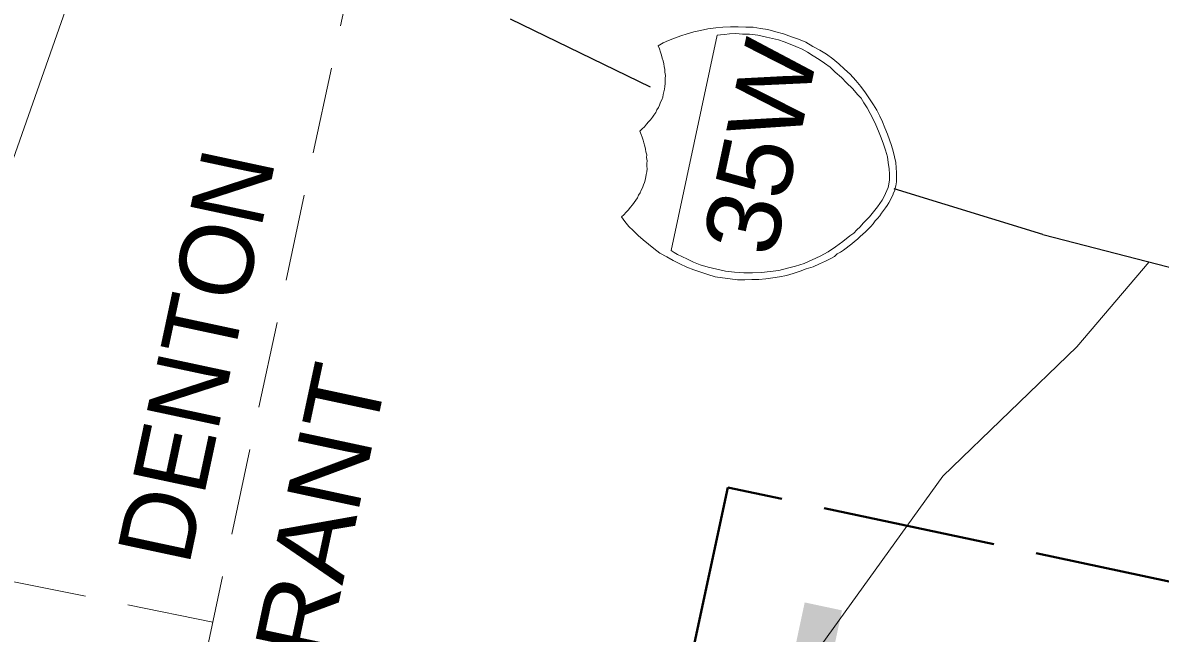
# Model space of a CAD drawing. Extents: x 2363411 to 2369126, y 6976878 to 6988319.
# Drawn here: x 2365792.5 to 2365871.2, y 6977116.7 to 6977159 of the extents above; entities that cross this region are included whole.
import ezdxf

# ---------------------------------------------------------------- set-up
doc = ezdxf.new("R2010")
doc.units = 0
doc.header["$LTSCALE"] = 2
doc.linetypes.add('LONG_DASHED', pattern=[7.5, 6, -1.5])
doc.linetypes.add('MEDIUM_DASHED', pattern=[4.5, 3, -1.5])
doc.layers.add('62', color=7, linetype='Continuous', lineweight=13)
doc.layers.add('63', color=7, linetype='Continuous', lineweight=13)

msp = doc.modelspace()

# ---------------------------------------------------------------- linework, layer by layer
at = {"layer": '62', "linetype": 'MEDIUM_DASHED'}
for p, q in [((2365864.629, 6977393.47), (2365770.962, 6976955.102)), ((2365805.658, 6977117.478), (2365712.699, 6977136.33))]:
    msp.add_line(p, q, dxfattribs=at)
at = {"layer": '62', "lineweight": 25}
for p, q in [((2365826.23, 6977159.266), (2365835.918, 6977154.55)), ((2365863.073, 6977144.33), (2365852.797, 6977147.493))]:
    msp.add_line(p, q, dxfattribs=at)
at = {"layer": '62'}
for points in [[(2365745.602, 6977025.615), (2365742.995, 6977037.011), (2365744.177, 6977051.369), (2365754.758, 6977065.562), (2365757.967, 6977076.059), (2365767.656, 6977087.91), (2365774.215, 6977096.102), (2365778.852, 6977103.376), (2365783.338, 6977114.034), (2365786.122, 6977122.873), (2365789.101, 6977134.663), (2365791.544, 6977148.682), (2365797.575, 6977165.918), (2365800.831, 6977177.279), (2365805.2, 6977190.083), (2365814.728, 6977203.211), (2365824.115, 6977215.605), (2365833.318, 6977226.804), (2365847.376, 6977238.756), (2365856.409, 6977246.882), (2365866.274, 6977257.086), (2365874.425, 6977262.384)], [(2365835.792, 6977152.114), (2365835.94, 6977152.269), (2365836.07, 6977152.447), (2365836.171, 6977152.585), (2365836.301, 6977152.764), (2365836.363, 6977152.957), (2365836.489, 6977153.115), (2365836.55, 6977153.286), (2365836.637, 6977153.474), (2365836.718, 6977153.64), (2365836.782, 6977153.835), (2365836.82, 6977154.011), (2365836.862, 6977154.209), (2365836.899, 6977154.385), (2365836.937, 6977154.561), (2365836.961, 6977154.785), (2365836.952, 6977154.948), (2365836.945, 6977155.134), (2365836.964, 6977155.338), (2365836.918, 6977155.555), (2365836.937, 6977155.737), (2365836.889, 6977155.954), (2365836.86, 6977156.144), (2365836.81, 6977156.339), (2365836.738, 6977156.54), (2365836.688, 6977156.735), (2365836.62, 6977156.954), (2365836.551, 6977157.175), (2365836.455, 6977157.38), (2365836.801, 6977157.582), (2365837.182, 6977157.756), (2365837.585, 6977157.922), (2365838.034, 6977158.079), (2365838.478, 6977158.213), (2365838.942, 6977158.345), (2365839.402, 6977158.454), (2365839.908, 6977158.554), (2365840.45, 6977158.622), (2365840.945, 6977158.676), (2365841.479, 6977158.699), (2365842.008, 6977158.703), (2365842.534, 6977158.682), (2365843.036, 6977158.667), (2365843.547, 6977158.58), (2365844.063, 6977158.517), (2365844.605, 6977158.354), (2365845.15, 6977158.215), (2365845.681, 6977158.01), (2365846.171, 6977157.836), (2365846.682, 6977157.634), (2365847.172, 6977157.346), (2365847.647, 6977157.085), (2365848.114, 6977156.801), (2365848.551, 6977156.476), (2365848.962, 6977156.137), (2365849.366, 6977155.772), (2365849.75, 6977155.414), (2365850.141, 6977154.985), (2365850.489, 6977154.565), (2365850.811, 6977154.128), (2365851.143, 6977153.646), (2365851.369, 6977153.297), (2365851.589, 6977152.927), (2365851.801, 6977152.514), (2365851.992, 6977152.125), (2365852.155, 6977151.7), (2365852.339, 6977151.27), (2365852.483, 6977150.871), (2365852.607, 6977150.476), (2365852.73, 6977150.082), (2365852.83, 6977149.692), (2365852.91, 6977149.309), (2365852.944, 6977148.932), (2365852.967, 6977148.604), (2365852.967, 6977148.283), (2365852.966, 6977147.962), (2365852.911, 6977147.697)], [(2365852.911, 6977147.697), (2365852.874, 6977147.521), (2365852.839, 6977147.367), (2365852.759, 6977147.202), (2365852.703, 6977147.051), (2365852.621, 6977146.884), (2365852.539, 6977146.718), (2365852.428, 6977146.512), (2365852.318, 6977146.329), (2365852.192, 6977146.17), (2365852.062, 6977145.991), (2365851.927, 6977145.791), (2365851.797, 6977145.61), (2365851.641, 6977145.417), (2365851.492, 6977145.262), (2365851.334, 6977145.065), (2365851.179, 6977144.871), (2365851.005, 6977144.7), (2365850.804, 6977144.514), (2365850.628, 6977144.343), (2365850.433, 6977144.178), (2365850.26, 6977144.006), (2365850.041, 6977143.844), (2365849.865, 6977143.675), (2365849.674, 6977143.532), (2365849.477, 6977143.368), (2365849.287, 6977143.224), (2365849.073, 6977143.086), (2365848.862, 6977142.971), (2365848.667, 6977142.804), (2365848.457, 6977142.688), (2365848.276, 6977142.589), (2365848.045, 6977142.477), (2365847.636, 6977142.288), (2365847.181, 6977142.087), (2365846.709, 6977141.936), (2365846.282, 6977141.77), (2365845.812, 6977141.619), (2365845.349, 6977141.491), (2365844.867, 6977141.385), (2365844.393, 6977141.325), (2365843.916, 6977141.243), (2365843.424, 6977141.209), (2365842.941, 6977141.197), (2365842.454, 6977141.187), (2365841.948, 6977141.18), (2365841.454, 6977141.239), (2365840.916, 6977141.309), (2365840.404, 6977141.394), (2365839.907, 6977141.547), (2365839.412, 6977141.7), (2365838.941, 6977141.87), (2365838.453, 6977142.064), (2365837.971, 6977142.282), (2365837.495, 6977142.523), (2365837.064, 6977142.776), (2365836.591, 6977143.037), (2365836.177, 6977143.356), (2365835.801, 6977143.641), (2365835.431, 6977143.953), (2365835.08, 6977144.257), (2365834.742, 6977144.606), (2365834.431, 6977144.881), (2365834.156, 6977145.214), (2365833.927, 6977145.539), (2365834.096, 6977145.689), (2365834.25, 6977145.862), (2365834.402, 6977146.036), (2365834.529, 6977146.193), (2365834.679, 6977146.368), (2365834.805, 6977146.525), (2365834.915, 6977146.708), (2365835.041, 6977146.865), (2365835.1, 6977147.037), (2365835.224, 6977147.196), (2365835.289, 6977147.389), (2365835.371, 6977147.556), (2365835.461, 6977147.765), (2365835.518, 6977147.917), (2365835.555, 6977148.093), (2365835.603, 6977148.312), (2365835.64, 6977148.486), (2365835.678, 6977148.664), (2365835.698, 6977148.868), (2365835.692, 6977149.051), (2365835.684, 6977149.237), (2365835.699, 6977149.418), (2365835.661, 6977149.659), (2365835.674, 6977149.838), (2365835.624, 6977150.033), (2365835.597, 6977150.223), (2365835.551, 6977150.439), (2365835.482, 6977150.661), (2365835.431, 6977150.856), (2365835.36, 6977151.057), (2365835.286, 6977151.255), (2365835.194, 6977151.483), (2365835.366, 6977151.63), (2365835.516, 6977151.78), (2365835.669, 6977151.956), (2365835.792, 6977152.114)], [(2365832.332, 6977103.289), (2365834.117, 6977103.46), (2365839.362, 6977109.264), (2365847.746, 6977115.874), (2365856.16, 6977127.585), (2365865.436, 6977136.53), (2365870.448, 6977142.431)]]:
    msp.add_lwpolyline(points, dxfattribs=at)
msp.add_lwpolyline([(2365840.551, 6977158.116), (2365837.366, 6977143.219), (2365837.569, 6977143.084), (2365837.811, 6977142.938), (2365838.103, 6977142.785), (2365838.5, 6977142.606), (2365838.918, 6977142.404), (2365839.382, 6977142.211), (2365839.922, 6977142.049), (2365840.519, 6977141.921), (2365841.135, 6977141.79), (2365841.759, 6977141.704), (2365842.394, 6977141.66), (2365842.994, 6977141.669), (2365843.619, 6977141.697), (2365844.208, 6977141.755), (2365844.823, 6977141.83), (2365845.407, 6977141.981), (2365845.971, 6977142.137), (2365846.56, 6977142.312), (2365847.118, 6977142.561), (2365847.679, 6977142.809), (2365848.229, 6977143.127), (2365848.743, 6977143.477), (2365849.254, 6977143.83), (2365849.732, 6977144.235), (2365849.998, 6977144.408), (2365850.209, 6977144.639), (2365850.436, 6977144.844), (2365850.653, 6977145.096), (2365850.859, 6977145.308), (2365851.09, 6977145.532), (2365851.279, 6977145.77), (2365851.467, 6977146.004), (2365851.635, 6977146.244), (2365851.795, 6977146.464), (2365851.961, 6977146.704), (2365852.074, 6977146.909), (2365852.197, 6977147.159), (2365852.289, 6977147.37), (2365852.379, 6977147.578), (2365852.426, 6977147.801), (2365852.469, 6977148.111), (2365852.484, 6977148.501), (2365852.447, 6977148.876), (2365852.38, 6977149.306), (2365852.327, 6977149.708), (2365852.192, 6977150.152), (2365852.052, 6977150.575), (2365851.894, 6977151.021), (2365851.715, 6977151.475), (2365851.532, 6977151.903), (2365851.343, 6977152.313), (2365851.126, 6977152.705), (2365850.932, 6977153.09), (2365850.708, 6977153.439), (2365850.503, 6977153.759), (2365850.276, 6977153.991), (2365849.909, 6977154.437), (2365849.509, 6977154.822), (2365849.149, 6977155.197), (2365848.724, 6977155.564), (2365848.358, 6977155.896), (2365847.982, 6977156.183), (2365847.601, 6977156.448), (2365847.194, 6977156.697), (2365846.788, 6977156.945), (2365846.419, 6977157.161), (2365845.998, 6977157.343), (2365845.594, 6977157.501), (2365845.19, 6977157.655), (2365844.782, 6977157.789), (2365844.368, 6977157.898), (2365843.952, 6977157.987), (2365843.357, 6977158.114), (2365842.797, 6977158.191), (2365842.294, 6977158.204), (2365841.84, 6977158.231), (2365841.399, 6977158.211), (2365841.066, 6977158.168), (2365840.783, 6977158.136)], close=True, dxfattribs=at)
at = {"layer": '62', "lineweight": 25}
msp.add_lwpolyline([(2365863.073, 6977144.33), (2365906.797, 6977133.032), (2365917.348, 6977132.661)], dxfattribs=at)
at = {"layer": '62', "linetype": 'LONG_DASHED', "lineweight": 40}
msp.add_lwpolyline([(2365804.964, 6976956.79), (2365867.37, 6976943.454), (2365903.697, 6977113.468), (2365841.291, 6977126.802), (2365804.897, 6976956.481)], dxfattribs=at)
at = {"layer": '63', "linetype": 'MEDIUM_DASHED'}
for p, q in [((2365864.629, 6977393.47), (2365770.962, 6976955.102)), ((2365805.658, 6977117.478), (2365712.699, 6977136.33))]:
    msp.add_line(p, q, dxfattribs=at)
at = {"layer": '63', "lineweight": 25}
for p, q in [((2365826.23, 6977159.266), (2365835.918, 6977154.55)), ((2365863.073, 6977144.33), (2365852.797, 6977147.493))]:
    msp.add_line(p, q, dxfattribs=at)
at = {"layer": '63'}
for points in [[(2365745.602, 6977025.615), (2365742.995, 6977037.011), (2365744.177, 6977051.369), (2365754.758, 6977065.562), (2365757.967, 6977076.059), (2365767.656, 6977087.91), (2365774.215, 6977096.102), (2365778.852, 6977103.376), (2365783.338, 6977114.034), (2365786.122, 6977122.873), (2365789.101, 6977134.663), (2365791.544, 6977148.682), (2365797.575, 6977165.918), (2365800.831, 6977177.279), (2365805.2, 6977190.083), (2365814.728, 6977203.211), (2365824.115, 6977215.605), (2365833.318, 6977226.804), (2365847.376, 6977238.756), (2365856.409, 6977246.882), (2365866.274, 6977257.086), (2365874.425, 6977262.384)], [(2365835.792, 6977152.114), (2365835.94, 6977152.269), (2365836.07, 6977152.447), (2365836.171, 6977152.585), (2365836.301, 6977152.764), (2365836.363, 6977152.957), (2365836.489, 6977153.115), (2365836.55, 6977153.286), (2365836.637, 6977153.474), (2365836.718, 6977153.64), (2365836.782, 6977153.835), (2365836.82, 6977154.011), (2365836.862, 6977154.209), (2365836.899, 6977154.385), (2365836.937, 6977154.561), (2365836.961, 6977154.785), (2365836.952, 6977154.948), (2365836.945, 6977155.134), (2365836.964, 6977155.338), (2365836.918, 6977155.555), (2365836.937, 6977155.737), (2365836.889, 6977155.954), (2365836.86, 6977156.144), (2365836.81, 6977156.339), (2365836.738, 6977156.54), (2365836.688, 6977156.735), (2365836.62, 6977156.954), (2365836.551, 6977157.175), (2365836.455, 6977157.38), (2365836.801, 6977157.582), (2365837.182, 6977157.756), (2365837.585, 6977157.922), (2365838.034, 6977158.079), (2365838.478, 6977158.213), (2365838.942, 6977158.345), (2365839.402, 6977158.454), (2365839.908, 6977158.554), (2365840.45, 6977158.622), (2365840.945, 6977158.676), (2365841.479, 6977158.699), (2365842.008, 6977158.703), (2365842.534, 6977158.682), (2365843.036, 6977158.667), (2365843.547, 6977158.58), (2365844.063, 6977158.517), (2365844.605, 6977158.354), (2365845.15, 6977158.215), (2365845.681, 6977158.01), (2365846.171, 6977157.836), (2365846.682, 6977157.634), (2365847.172, 6977157.346), (2365847.647, 6977157.085), (2365848.114, 6977156.801), (2365848.551, 6977156.476), (2365848.962, 6977156.137), (2365849.366, 6977155.772), (2365849.75, 6977155.414), (2365850.141, 6977154.985), (2365850.489, 6977154.565), (2365850.811, 6977154.128), (2365851.143, 6977153.646), (2365851.369, 6977153.297), (2365851.589, 6977152.927), (2365851.801, 6977152.514), (2365851.992, 6977152.125), (2365852.155, 6977151.7), (2365852.339, 6977151.27), (2365852.483, 6977150.871), (2365852.607, 6977150.476), (2365852.73, 6977150.082), (2365852.83, 6977149.692), (2365852.91, 6977149.309), (2365852.944, 6977148.932), (2365852.967, 6977148.604), (2365852.967, 6977148.283), (2365852.966, 6977147.962), (2365852.911, 6977147.697)], [(2365852.911, 6977147.697), (2365852.874, 6977147.521), (2365852.839, 6977147.367), (2365852.759, 6977147.202), (2365852.703, 6977147.051), (2365852.621, 6977146.884), (2365852.539, 6977146.718), (2365852.428, 6977146.512), (2365852.318, 6977146.329), (2365852.192, 6977146.17), (2365852.062, 6977145.991), (2365851.927, 6977145.791), (2365851.797, 6977145.61), (2365851.641, 6977145.417), (2365851.492, 6977145.262), (2365851.334, 6977145.065), (2365851.179, 6977144.871), (2365851.005, 6977144.7), (2365850.804, 6977144.514), (2365850.628, 6977144.343), (2365850.433, 6977144.178), (2365850.26, 6977144.006), (2365850.041, 6977143.844), (2365849.865, 6977143.675), (2365849.674, 6977143.532), (2365849.477, 6977143.368), (2365849.287, 6977143.224), (2365849.073, 6977143.086), (2365848.862, 6977142.971), (2365848.667, 6977142.804), (2365848.457, 6977142.688), (2365848.276, 6977142.589), (2365848.045, 6977142.477), (2365847.636, 6977142.288), (2365847.181, 6977142.087), (2365846.709, 6977141.936), (2365846.282, 6977141.77), (2365845.812, 6977141.619), (2365845.349, 6977141.491), (2365844.867, 6977141.385), (2365844.393, 6977141.325), (2365843.916, 6977141.243), (2365843.424, 6977141.209), (2365842.941, 6977141.197), (2365842.454, 6977141.187), (2365841.948, 6977141.18), (2365841.454, 6977141.239), (2365840.916, 6977141.309), (2365840.404, 6977141.394), (2365839.907, 6977141.547), (2365839.412, 6977141.7), (2365838.941, 6977141.87), (2365838.453, 6977142.064), (2365837.971, 6977142.282), (2365837.495, 6977142.523), (2365837.064, 6977142.776), (2365836.591, 6977143.037), (2365836.177, 6977143.356), (2365835.801, 6977143.641), (2365835.431, 6977143.953), (2365835.08, 6977144.257), (2365834.742, 6977144.606), (2365834.431, 6977144.881), (2365834.156, 6977145.214), (2365833.927, 6977145.539), (2365834.096, 6977145.689), (2365834.25, 6977145.862), (2365834.402, 6977146.036), (2365834.529, 6977146.193), (2365834.679, 6977146.368), (2365834.805, 6977146.525), (2365834.915, 6977146.708), (2365835.041, 6977146.865), (2365835.1, 6977147.037), (2365835.224, 6977147.196), (2365835.289, 6977147.389), (2365835.371, 6977147.556), (2365835.461, 6977147.765), (2365835.518, 6977147.917), (2365835.555, 6977148.093), (2365835.603, 6977148.312), (2365835.64, 6977148.486), (2365835.678, 6977148.664), (2365835.698, 6977148.868), (2365835.692, 6977149.051), (2365835.684, 6977149.237), (2365835.699, 6977149.418), (2365835.661, 6977149.659), (2365835.674, 6977149.838), (2365835.624, 6977150.033), (2365835.597, 6977150.223), (2365835.551, 6977150.439), (2365835.482, 6977150.661), (2365835.431, 6977150.856), (2365835.36, 6977151.057), (2365835.286, 6977151.255), (2365835.194, 6977151.483), (2365835.366, 6977151.63), (2365835.516, 6977151.78), (2365835.669, 6977151.956), (2365835.792, 6977152.114)], [(2365832.332, 6977103.289), (2365834.117, 6977103.46), (2365839.362, 6977109.264), (2365847.746, 6977115.874), (2365856.16, 6977127.585), (2365865.436, 6977136.53), (2365870.448, 6977142.431)]]:
    msp.add_lwpolyline(points, dxfattribs=at)
msp.add_lwpolyline([(2365840.551, 6977158.116), (2365837.366, 6977143.219), (2365837.569, 6977143.084), (2365837.811, 6977142.938), (2365838.103, 6977142.785), (2365838.5, 6977142.606), (2365838.918, 6977142.404), (2365839.382, 6977142.211), (2365839.922, 6977142.049), (2365840.519, 6977141.921), (2365841.135, 6977141.79), (2365841.759, 6977141.704), (2365842.394, 6977141.66), (2365842.994, 6977141.669), (2365843.619, 6977141.697), (2365844.208, 6977141.755), (2365844.823, 6977141.83), (2365845.407, 6977141.981), (2365845.971, 6977142.137), (2365846.56, 6977142.312), (2365847.118, 6977142.561), (2365847.679, 6977142.809), (2365848.229, 6977143.127), (2365848.743, 6977143.477), (2365849.254, 6977143.83), (2365849.732, 6977144.235), (2365849.998, 6977144.408), (2365850.209, 6977144.639), (2365850.436, 6977144.844), (2365850.653, 6977145.096), (2365850.859, 6977145.308), (2365851.09, 6977145.532), (2365851.279, 6977145.77), (2365851.467, 6977146.004), (2365851.635, 6977146.244), (2365851.795, 6977146.464), (2365851.961, 6977146.704), (2365852.074, 6977146.909), (2365852.197, 6977147.159), (2365852.289, 6977147.37), (2365852.379, 6977147.578), (2365852.426, 6977147.801), (2365852.469, 6977148.111), (2365852.484, 6977148.501), (2365852.447, 6977148.876), (2365852.38, 6977149.306), (2365852.327, 6977149.708), (2365852.192, 6977150.152), (2365852.052, 6977150.575), (2365851.894, 6977151.021), (2365851.715, 6977151.475), (2365851.532, 6977151.903), (2365851.343, 6977152.313), (2365851.126, 6977152.705), (2365850.932, 6977153.09), (2365850.708, 6977153.439), (2365850.503, 6977153.759), (2365850.276, 6977153.991), (2365849.909, 6977154.437), (2365849.509, 6977154.822), (2365849.149, 6977155.197), (2365848.724, 6977155.564), (2365848.358, 6977155.896), (2365847.982, 6977156.183), (2365847.601, 6977156.448), (2365847.194, 6977156.697), (2365846.788, 6977156.945), (2365846.419, 6977157.161), (2365845.998, 6977157.343), (2365845.594, 6977157.501), (2365845.19, 6977157.655), (2365844.782, 6977157.789), (2365844.368, 6977157.898), (2365843.952, 6977157.987), (2365843.357, 6977158.114), (2365842.797, 6977158.191), (2365842.294, 6977158.204), (2365841.84, 6977158.231), (2365841.399, 6977158.211), (2365841.066, 6977158.168), (2365840.783, 6977158.136)], close=True, dxfattribs=at)
at = {"layer": '63', "lineweight": 25}
msp.add_lwpolyline([(2365863.073, 6977144.33), (2365906.797, 6977133.032), (2365917.348, 6977132.661)], dxfattribs=at)
at = {"layer": '63', "linetype": 'LONG_DASHED', "lineweight": 40}
msp.add_lwpolyline([(2365804.964, 6976956.79), (2365867.37, 6976943.454), (2365903.697, 6977113.468), (2365841.291, 6977126.802), (2365804.897, 6976956.481)], dxfattribs=at)

# ---------------------------------------------------------------- texts
at = {"layer": '62'}
for s, height, width, p in [('35W', 5.099, 1.05, (2365844.49, 6977142.64)), ('TARRANT', 5.099, 1.1, (2365810.346, 6977100.003)), ('PROJECT', 23.83, 1.1, (2365835.896, 6976954.668))]:
    msp.add_text(s, height=height, rotation=77.939, dxfattribs=dict(at, width=width)).set_placement(p)
msp.add_text('DENTON', height=5.099, rotation=77.939, dxfattribs=at).set_placement((2365803.987, 6977121.289))
at = {"layer": '63'}
for s, height, width, p in [('35W', 5.099, 1.05, (2365844.49, 6977142.64)), ('TARRANT', 5.099, 1.1, (2365810.346, 6977100.003)), ('PROJECT', 23.83, 1.1, (2365835.896, 6976954.668))]:
    msp.add_text(s, height=height, rotation=77.939, dxfattribs=dict(at, width=width)).set_placement(p)
msp.add_text('DENTON', height=5.099, rotation=77.939, dxfattribs=at).set_placement((2365803.987, 6977121.289))

doc.saveas('drawing.dxf')
